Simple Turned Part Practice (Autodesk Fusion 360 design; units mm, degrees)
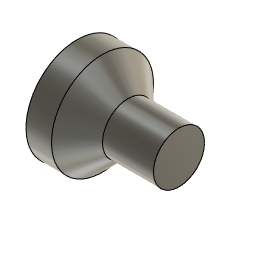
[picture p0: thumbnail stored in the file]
sketch "Sketch1" plane through (0, 0, 0) normal (0, 1, 0) x axis (1, 0, 0)
  line L1 (50.8, 0) -> (0, 0)
  line L2 (0, -25.4) -> (0, 0)
  line L3 (12.7, -25.4) -> (0, -25.4)
  line L4 (25.4, -12.7) -> (12.7, -25.4)
  line L5 (50.8, -12.7) -> (25.4, -12.7)
  line L6 (50.8, 0) -> (50.8, -12.7)
  point P1 (0, 0)
  point P2 (0, 0)
  point P4 (0, 0)
  point P5 (0, -25.4)
  point P6 (12.7, -25.4)
  point P3 (50.8, 0)
  point P7 (25.4, -12.7)
  point P8 (50.8, -12.7)
  coincident P1 P2
  horizontal L1
  coincident P1 P4
  perpendicular L1 L2
  perpendicular L2 L3
  parallel L1 L5
  perpendicular L1 L6
  dimension "d1" distance P4 P5 = 25.4
  dimension "d2" distance P5 P6 = 12.7
  dimension "d3" = 25.4
  dimension "d4" distance P2 P3 = 50.8
  dimension "d5" distance P7 P8 = 25.4
revolve "Revolve1" sketch "Sketch1" AlongAngle 360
